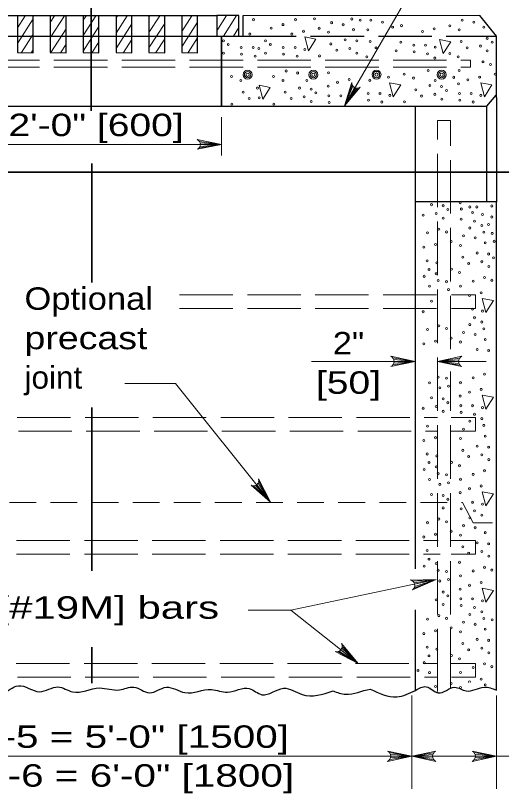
# Model space of a CAD drawing. Extents: x 1329.9 to 1363.9, y 715.5 to 737.5.
# Drawn here: x 1335.14 to 1338.52, y 728.7 to 734.11 of the extents above; entities that cross this region are included whole.
import ezdxf
from ezdxf.enums import TextEntityAlignment as Align

# ---------------------------------------------------------------- set-up
doc = ezdxf.new("R2010")
doc.units = 0
doc.header["$LTSCALE"] = 0.062
doc.linetypes.add('LONG_DASHED', pattern=[7.5, 6, -1.5])
doc.linetypes.add('MEDIUM_DASHED', pattern=[4.5, 3, -1.5])
doc.layers.add('1', color=7, linetype='Continuous', lineweight=13)

msp = doc.modelspace()

# ---------------------------------------------------------------- linework, layer by layer
at = {"layer": '1', "lineweight": 35}
for p, q in [((1335.66467, 735.20608), (1335.66467, 733.44408)), ((1335.66942, 733.07875), (1335.66942, 732.2515)), ((1335.66942, 731.38008), (1335.66942, 730.24558))]:
    msp.add_line(p, q, dxfattribs=at)
at = {"layer": '1', "lineweight": 25}
for p, q in [((1334.80542, 734.10575), (1336.53992, 734.10575)), ((1336.69283, 734.10575), (1336.53992, 734.10575)), ((1336.54033, 734.10575), (1336.54033, 733.96325)), ((1336.69283, 733.96325), (1336.69283, 734.10575)), ((1336.72025, 734.10508), (1336.72025, 733.96325)), ((1334.80125, 733.96325), (1336.54408, 733.96325)), ((1338.41808, 733.47675), (1338.48275, 733.55208)), ((1338.4845, 733.53675), (1338.4845, 732.81242)), ((1334.76992, 733.47708), (1336.57183, 733.47708)), ((1336.57192, 733.47717), (1338.41808, 733.47675)), ((1337.91867, 733.47675), (1337.91867, 730.259)), ((1338.41808, 732.81183), (1338.41808, 733.47675)), ((1338.4845, 732.81242), (1337.91867, 732.81242))]:
    msp.add_line(p, q, dxfattribs=at)
at = {"layer": '1'}
for p, q in [((1335.15233, 734.02008), (1335.20717, 734.1055)), ((1335.381, 733.951), (1335.48017, 734.10533)), ((1335.49117, 734.10533), (1335.38117, 734.10575)), ((1335.38117, 734.05867), (1335.41133, 734.10567)), ((1335.60983, 734.07442), (1335.62992, 734.10567)), ((1335.60983, 733.96683), (1335.69883, 734.10542)), ((1335.71992, 734.10533), (1335.61, 734.10575)), ((1335.83858, 733.98408), (1335.91658, 734.1055)), ((1335.83867, 734.09175), (1335.84767, 734.10567)), ((1335.94875, 734.10533), (1335.83875, 734.10575)), ((1336.06742, 733.9885), (1336.1425, 734.1055)), ((1336.1775, 734.10533), (1336.0675, 734.10575)), ((1336.0675, 734.09617), (1336.07358, 734.10567)), ((1336.29625, 734.10375), (1336.2975, 734.10567)), ((1336.29625, 733.99625), (1336.36633, 734.1055)), ((1336.40625, 734.10533), (1336.29633, 734.10575)), ((1336.54033, 734.00025), (1336.60817, 734.10575)), ((1336.58567, 733.96325), (1336.67725, 734.10575)), ((1335.15217, 733.9125), (1335.26233, 734.08392)), ((1335.83842, 733.87642), (1335.94858, 734.04792)), ((1336.06725, 733.881), (1336.17742, 734.05242)), ((1336.29608, 733.88858), (1336.40617, 734.06)), ((1335.38433, 733.84867), (1335.491, 734.01483)), ((1335.60967, 733.85917), (1335.71983, 734.03067)), ((1336.65467, 733.96325), (1336.69283, 734.02275)), ((1335.18025, 733.84867), (1335.26217, 733.97625)), ((1335.88958, 733.8485), (1335.9485, 733.94025)), ((1336.1155, 733.8485), (1336.17725, 733.94475)), ((1336.33942, 733.84858), (1336.406, 733.95233)), ((1336.57225, 733.96325), (1336.57225, 733.48492)), ((1336.68917, 733.96325), (1336.69283, 733.969)), ((1335.45317, 733.84842), (1335.49092, 733.90717)), ((1335.67183, 733.8485), (1335.71967, 733.923)), ((1335.24908, 733.84833), (1335.26208, 733.86858)), ((1335.48758, 733.84833), (1335.49083, 733.85342)), ((1338.30508, 733.79608), (1338.23917, 733.79608)), ((1338.30508, 733.74733), (1338.30508, 733.79608)), ((1338.30508, 733.74733), (1338.23775, 733.74733)), ((1336.83392, 733.62175), (1336.85958, 733.52442)), ((1337.48083, 733.6245), (1337.42808, 733.47783)), ((1337.48675, 733.61467), (1337.42808, 733.47783)), ((1337.4975, 733.60583), (1337.42808, 733.47783)), ((1337.50767, 733.60208), (1337.42808, 733.47783)), ((1337.51942, 733.60158), (1337.42808, 733.47783)), ((1336.57183, 733.40058), (1336.57183, 733.13242)), ((1336.41958, 733.2315), (1336.57183, 733.21025)), ((1336.41775, 733.18667), (1336.57183, 733.21025)), ((1336.42358, 733.19658), (1336.57183, 733.21025)), ((1336.42475, 733.221), (1336.57183, 733.21025)), ((1336.42633, 733.21025), (1336.57183, 733.21025)), ((1336.47292, 733.21025), (1336.57183, 733.21025)), ((1337.76458, 731.7265), (1337.91867, 731.7015)), ((1337.77042, 731.716), (1337.91867, 731.7015)), ((1338.22767, 731.72408), (1338.07542, 731.7015)), ((1337.19883, 731.7015), (1337.91867, 731.7015)), ((1337.76642, 731.679), (1337.91867, 731.7015)), ((1337.77158, 731.69017), (1337.91867, 731.7015)), ((1337.77317, 731.7015), (1337.91867, 731.7015)), ((1338.22258, 731.71292), (1338.07542, 731.7015)), ((1338.07542, 731.7015), (1338.41317, 731.7015)), ((1338.221, 731.7015), (1338.07542, 731.7015)), ((1338.22367, 731.68708), (1338.07542, 731.7015)), ((1338.2295, 731.67658), (1338.07542, 731.7015)), ((1336.25325, 731.54808), (1335.90092, 731.54808)), ((1336.91233, 730.7235), (1336.25325, 731.54808)), ((1336.82733, 730.855), (1336.91233, 730.7235)), ((1336.83108, 730.86633), (1336.91233, 730.7235)), ((1336.79783, 730.83533), (1336.91233, 730.7235)), ((1336.80925, 730.838), (1336.91233, 730.7235)), ((1336.81858, 730.84375), (1336.91233, 730.7235)), ((1337.05458, 729.97233), (1338.06583, 730.18458)), ((1337.90442, 730.17258), (1338.06583, 730.18458)), ((1337.91208, 730.16283), (1338.06583, 730.18458)), ((1337.91258, 730.126), (1338.06583, 730.18458)), ((1337.91608, 730.15217), (1338.06583, 730.18458)), ((1337.91633, 730.1375), (1338.06583, 730.18458)), ((1337.05458, 729.97233), (1336.75858, 729.97267)), ((1337.05458, 729.97233), (1337.52267, 729.60117)), ((1337.41175, 729.71908), (1337.52267, 729.60117)), ((1337.38075, 729.6835), (1337.52267, 729.60117)), ((1337.392, 729.68775), (1337.52267, 729.60117)), ((1337.40325, 729.69717), (1337.52267, 729.60117)), ((1337.40908, 729.70708), (1337.52267, 729.60117)), ((1338.09108, 729.3975), (1338.06908, 729.40175)), ((1338.06908, 729.40175), (1338.06983, 729.39883)), ((1337.8955, 729.37808), (1337.8955, 728.82842)), ((1337.8955, 729.37542), (1337.8955, 728.72917)), ((1338.4845, 729.37808), (1338.4845, 728.82842)), ((1338.4845, 729.37542), (1338.4845, 728.72917)), ((1337.23308, 728.95625), (1333.43842, 728.95625)), ((1337.8955, 728.95625), (1337.23308, 728.95625)), ((1337.74142, 728.98125), (1337.8955, 728.95625)), ((1337.74325, 728.93375), (1337.8955, 728.95625)), ((1337.74725, 728.97075), (1337.8955, 728.95625)), ((1337.74842, 728.94492), (1337.8955, 728.95625)), ((1337.74992, 728.95625), (1337.8955, 728.95625)), ((1338.04783, 728.97883), (1337.8955, 728.95625)), ((1338.04267, 728.96767), (1337.8955, 728.95625)), ((1339.24542, 728.95625), (1337.8955, 728.95625)), ((1338.04108, 728.95625), (1337.8955, 728.95625)), ((1338.04375, 728.94183), (1337.8955, 728.95625)), ((1338.04958, 728.93133), (1337.8955, 728.95625)), ((1338.4845, 728.95625), (1338.23675, 728.95625)), ((1338.33042, 728.98125), (1338.4845, 728.95625)), ((1338.33225, 728.93375), (1338.4845, 728.95625)), ((1338.33625, 728.97075), (1338.4845, 728.95625)), ((1338.33742, 728.94492), (1338.4845, 728.95625)), ((1338.33892, 728.95625), (1338.4845, 728.95625))]:
    msp.add_line(p, q, dxfattribs=at)
at = {"layer": '1', "linetype": 'LONG_DASHED', "lineweight": 25}
msp.add_line((1336.72025, 733.96325), (1338.4845, 733.96325), dxfattribs=at)
at = {"layer": '1', "linetype": 'LONG_DASHED'}
for p, q in [((1333.04633, 733.79608), (1338.30508, 733.79608)), ((1333.04633, 733.74733), (1338.30508, 733.74733)), ((1338.07492, 733.37567), (1338.16467, 733.37567)), ((1338.16467, 731.78575), (1338.16467, 733.37567)), ((1336.28017, 732.1655), (1338.077, 732.1655)), ((1338.17267, 732.1655), (1338.34008, 732.1655)), ((1338.34008, 732.1655), (1338.34008, 732.07058)), ((1336.28017, 732.07058), (1338.077, 732.07058)), ((1338.17267, 732.07058), (1338.34008, 732.07058)), ((1333.26267, 731.31067), (1338.07467, 731.31067)), ((1338.17033, 731.31067), (1338.34008, 731.31067)), ((1338.34008, 731.31067), (1338.34008, 731.21567)), ((1333.27175, 731.21567), (1338.07467, 731.21567)), ((1338.16583, 731.21567), (1338.34008, 731.21567)), ((1333.25808, 730.45583), (1338.07925, 730.45583)), ((1338.16583, 730.45583), (1338.34008, 730.45583)), ((1338.34008, 730.45583), (1338.34008, 730.36083)), ((1333.25808, 730.36083), (1338.09292, 730.36083)), ((1338.17033, 730.36083), (1338.34008, 730.36083)), ((1333.25575, 729.60092), (1338.07692, 729.60092)), ((1338.168, 729.60092), (1338.34008, 729.60092)), ((1338.34008, 729.60092), (1338.34008, 729.50592)), ((1333.26492, 729.50592), (1338.07692, 729.50592)), ((1338.17258, 729.50592), (1338.34008, 729.50592))]:
    msp.add_line(p, q, dxfattribs=at)
at = {"layer": '1', "linetype": 'MEDIUM_DASHED'}
msp.add_line((1338.32433, 730.57925), (1338.45892, 730.57925), dxfattribs=at)
at = {"layer": '1'}
for points in [[(1338.59067, 735.00633), (1338.312, 735.00633), (1337.42808, 733.47783)], [(1336.85958, 733.52442), (1336.91183, 733.6065), (1336.83392, 733.62175)], [(1337.47867, 733.64175), (1337.42808, 733.47783), (1337.53783, 733.60967)], [(1336.40367, 733.17658), (1336.57183, 733.21025), (1336.40367, 733.24383)], [(1334.76992, 733.21025), (1335.88917, 733.21025), (1336.57183, 733.21025)], [(1337.7505, 731.73717), (1337.91867, 731.7015), (1337.7505, 731.66592)], [(1338.24367, 731.66592), (1338.07542, 731.7015), (1338.24367, 731.73717)], [(1336.82975, 730.88458), (1336.91233, 730.7235), (1336.77808, 730.84042)], [(1337.90025, 730.1125), (1338.06583, 730.18458), (1337.88525, 730.18167)], [(1337.3625, 729.6845), (1337.52267, 729.60117), (1337.40683, 729.73975)], [(1337.72733, 728.99192), (1337.8955, 728.95625), (1337.72733, 728.92067)], [(1338.06375, 728.92067), (1337.8955, 728.95625), (1338.06375, 728.99192)], [(1338.31633, 728.99192), (1338.4845, 728.95625), (1338.31633, 728.92067)]]:
    msp.add_lwpolyline(points, dxfattribs=at)
at = {"layer": '1', "lineweight": 25}
for points in [[(1335.15242, 734.10575), (1335.15208, 733.84867), (1335.262, 733.84825), (1335.26242, 734.10533)], [(1335.38117, 734.10575), (1335.38083, 733.84867), (1335.49083, 733.84825), (1335.49117, 734.10533)], [(1335.61, 734.10575), (1335.60958, 733.84867), (1335.71958, 733.84825), (1335.71992, 734.10533)], [(1335.83875, 734.10575), (1335.83842, 733.84867), (1335.94833, 733.84825), (1335.94875, 734.10533)], [(1336.0675, 734.10575), (1336.06717, 733.84867), (1336.17717, 733.84825), (1336.1775, 734.10533)], [(1336.29633, 734.10575), (1336.296, 733.84867), (1336.40592, 733.84825), (1336.40625, 734.10533)], [(1338.4845, 733.53708), (1338.4845, 733.96325), (1338.37, 734.1075), (1336.72025, 734.10508)], [(1336.54408, 733.96325), (1336.57183, 733.96325), (1336.72025, 733.96325)], [(1336.57183, 733.47708), (1336.57225, 733.96325), (1336.57183, 733.47708)], [(1338.4845, 729.41567), (1338.4845, 729.46942), (1338.4845, 732.81242)], [(1337.91867, 729.97317), (1337.91867, 729.46942), (1337.91867, 729.41567)]]:
    msp.add_lwpolyline(points, dxfattribs=at)
at = {"layer": '1'}
for points in [[(1337.15117, 733.9575), (1337.17675, 733.86025), (1337.229, 733.94242)], [(1338.08908, 733.93925), (1338.11467, 733.84192), (1338.16692, 733.92408)], [(1337.74183, 733.63892), (1337.76742, 733.54158), (1337.81967, 733.62375)], [(1338.37617, 733.63892), (1338.40183, 733.54158), (1338.454, 733.62375)], [(1338.38633, 732.13925), (1338.412, 732.04192), (1338.46417, 732.12408)], [(1338.38633, 731.46758), (1338.412, 731.37025), (1338.46417, 731.45242)], [(1338.38633, 730.79592), (1338.412, 730.69858), (1338.46417, 730.78083)], [(1338.38633, 730.12433), (1338.412, 730.02692), (1338.46417, 730.10908)]]:
    msp.add_lwpolyline(points, close=True, dxfattribs=at)
at = {"layer": '1', "linetype": 'LONG_DASHED'}
for points in [[(1338.07492, 729.40692), (1338.07492, 729.46942), (1338.07492, 733.37567)], [(1338.16467, 729.43033), (1338.16467, 729.46942), (1338.16467, 731.63233)]]:
    msp.add_lwpolyline(points, dxfattribs=at)
at = {"layer": '1', "lineweight": 35}
for points in [[(1332.47342, 733.01742), (1338.878, 733.01742), (1338.878, 732.60617)], [(1335.66942, 729.71392), (1335.66942, 729.46942), (1335.66942, 729.46508)]]:
    msp.add_lwpolyline(points, dxfattribs=at)
at = {"layer": '1', "linetype": 'MEDIUM_DASHED'}
msp.add_lwpolyline([(1333.095, 730.71958), (1338.24792, 730.71958), (1338.32433, 730.57925)], dxfattribs=at)
at = {"layer": '1'}
for centre, radius in [((1336.75365, 733.6949), 0.03133), ((1336.75365, 733.6949), 0.0219), ((1337.21106, 733.6949), 0.03133), ((1337.21106, 733.6949), 0.0219), ((1337.65078, 733.69625), 0.03133), ((1337.65078, 733.69625), 0.0219), ((1338.10442, 733.6949), 0.03133), ((1338.10442, 733.6949), 0.0219), ((1336.75365, 733.6949), 0.01122), ((1337.21106, 733.6949), 0.01122), ((1337.65078, 733.69625), 0.01122), ((1338.10442, 733.6949), 0.01122)]:
    msp.add_circle(centre, radius, dxfattribs=at)
for centre, radius, start, end in [((1337.51477, 733.63765), 0.03631, 173.62389, 309.45001), ((1336.39006, 733.21026), 0.03631, 292.08605, 67.91218), ((1337.8788, 730.1441), 0.03822, 304.32142, 80.14755), ((1337.37353, 729.7211), 0.03822, 253.29077, 29.1169)]:
    msp.add_arc(centre, radius, start, end, dxfattribs=at)
for centre in [(1336.79528, 734.07782), (1337.00013, 734.04357), (1337.08779, 734.07782), (1337.21884, 734.08415), (1337.33874, 734.05694), (1337.41952, 734.04273), (1337.47953, 734.08263), (1337.53689, 734.07441), (1337.6122, 734.07411), (1337.69298, 734.0599), (1337.82488, 734.03633), (1338.16006, 734.0351), (1338.2466, 734.07411), (1338.32738, 734.0599), (1336.91703, 734.01916), (1337.14345, 733.99706), (1337.2522, 734.01793), (1337.31733, 733.99073), (1337.48973, 734.00825), (1337.59079, 734.0079), (1337.76319, 734.02542), (1337.96989, 733.99519), (1338.05131, 734.01422), (1338.22519, 734.0079), (1338.39759, 734.02542), (1336.58603, 733.93118), (1336.76953, 733.97803), (1336.87854, 733.93118), (1337.06204, 733.97803), (1337.43211, 733.93818), (1337.51294, 733.93118), (1337.60623, 733.92629), (1338.24062, 733.92629), (1338.42079, 733.94835), (1336.61971, 733.90459), (1336.70964, 733.88372), (1336.7919, 733.88372), (1336.83112, 733.87739), (1336.91222, 733.90459), (1337.00214, 733.88372), (1337.0844, 733.88372), (1337.33277, 733.90913), (1337.46552, 733.87739), (1337.64736, 733.88275), (1337.82007, 733.92176), (1337.91, 733.90088), (1337.99226, 733.90088), (1338.05987, 733.88728), (1338.28175, 733.88275), (1338.37337, 733.89456), (1338.45447, 733.92176), (1336.58688, 733.84442), (1336.71217, 733.83748), (1336.80559, 733.82388), (1336.87939, 733.84442), (1337.00468, 733.83748), (1337.09809, 733.82388), (1337.15202, 733.87012), (1337.25394, 733.82567), (1337.3739, 733.86558), (1337.51378, 733.84442), (1337.58392, 733.81928), (1337.78724, 733.86159), (1337.91253, 733.85465), (1338.00595, 733.84105), (1338.1618, 733.84284), (1338.21831, 733.81928), (1338.42164, 733.86159), (1338.05644, 733.81111), (1338.39166, 733.78452), (1338.4439, 733.76549), (1337.02154, 733.72112), (1338.01018, 733.72407), (1338.22519, 733.72491), (1336.6425, 733.68211), (1336.70763, 733.65491), (1336.935, 733.68211), (1337.00013, 733.65491), (1337.10232, 733.70691), (1337.16504, 733.65491), (1337.31733, 733.70774), (1337.46065, 733.66123), (1337.60475, 733.65626), (1337.73411, 733.6784), (1337.84286, 733.69928), (1337.90799, 733.67208), (1338.0584, 733.65491), (1338.18776, 733.67705), (1338.28709, 733.65937), (1338.36851, 733.6784), (1338.47726, 733.69928), (1336.8224, 733.60235), (1337.11491, 733.60235), (1337.31421, 733.615), (1337.37924, 733.6422), (1338.02276, 733.61952), (1338.10359, 733.61252), (1338.22207, 733.63217), (1336.72306, 733.5733), (1337.01557, 733.5733), (1337.19574, 733.59536), (1337.22941, 733.56877), (1337.31934, 733.54789), (1337.4016, 733.54789), (1337.5928, 733.56506), (1337.67506, 733.56506), (1337.74267, 733.55146), (1337.92343, 733.59047), (1337.96456, 733.54693), (1338.05617, 733.55874), (1338.13727, 733.58594), (1338.2272, 733.56506), (1338.30946, 733.56506), (1338.37707, 733.55146), (1336.76419, 733.52976), (1336.83482, 733.53429), (1337.0567, 733.52976), (1337.14832, 733.54157), (1337.19658, 733.5086), (1337.32188, 733.50166), (1337.59534, 733.51883), (1337.68875, 733.50523), (1337.8446, 733.50702), (1338.10444, 733.52577), (1338.22973, 733.51883), (1338.32315, 733.50523), (1336.64424, 733.48985), (1336.93675, 733.48985), (1338.03292, 732.79151), (1338.23223, 732.80416), (1338.11375, 732.78452), (1338.14743, 732.75793), (1338.24107, 732.76145), (1338.30052, 732.77539), (1338.31961, 732.73705), (1338.34882, 732.77539), (1338.45286, 732.78236), (1337.97471, 732.71892), (1338.06633, 732.73073), (1338.1146, 732.69776), (1338.23989, 732.69082), (1338.38723, 732.72345), (1338.45286, 732.70569), (1338.29984, 732.62914), (1338.33331, 732.67722), (1338.38379, 732.64728), (1338.43056, 732.65342), (1338.0058, 732.59534), (1338.08462, 732.62069), (1338.13685, 732.60166), (1338.25676, 732.57446), (1338.39754, 732.60015), (1338.4549, 732.59192), (1338.17021, 732.53545), (1338.33754, 732.56024), (1338.40774, 732.52577), (1338.46944, 732.53668), (1337.98005, 732.49554), (1338.06147, 732.51457), (1338.23535, 732.50825), (1338.25078, 732.42664), (1338.35012, 732.45569), (1338.43095, 732.4487), (1338.46463, 732.42211), (1338.00242, 732.40123), (1338.07003, 732.38763), (1338.29191, 732.3831), (1338.38353, 732.39491), (1338.4318, 732.36194), (1338.01611, 732.3414), (1338.0666, 732.31146), (1338.17196, 732.34319), (1338.22847, 732.31963), (1337.98264, 732.29332), (1338.08034, 732.26433), (1338.1377, 732.2561), (1338.323, 732.25951), (1338.40182, 732.28487), (1338.45405, 732.26584), (1338.02034, 732.22442), (1338.15224, 732.20086), (1338.23535, 732.22526), (1338.29725, 732.15972), (1338.37867, 732.17875), (1338.03292, 732.11987), (1337.97471, 732.04727), (1338.31961, 732.06541), (1338.38723, 732.05181), (1338.33331, 732.00558), (1338.0058, 731.92369), (1338.08462, 731.94905), (1338.13685, 731.93002), (1338.29984, 731.9575), (1338.38379, 731.97563), (1338.39754, 731.92851), (1338.25676, 731.90282), (1338.33754, 731.8886), (1337.98005, 731.8239), (1338.06147, 731.84293), (1338.17021, 731.8638), (1338.23535, 731.8366), (1338.40774, 731.85412), (1338.35012, 731.78405), (1338.43095, 731.77705), (1338.40182, 731.61322), (1338.02034, 731.55278), (1338.08034, 731.59268), (1338.1377, 731.58446), (1338.23535, 731.55362), (1338.323, 731.58787), (1338.09054, 731.5183), (1338.15224, 731.52921), (1338.37867, 731.5071), (1338.03292, 731.44822), (1338.11375, 731.44123), (1338.23223, 731.46087), (1338.29725, 731.48807), (1338.06633, 731.38744), (1338.14743, 731.41464), (1338.23735, 731.39376), (1338.31961, 731.39376), (1337.97471, 731.37563), (1338.1146, 731.35447), (1338.23989, 731.34753), (1338.33331, 731.33393), (1338.38723, 731.38016), (1338.29984, 731.28585), (1338.38379, 731.30399), (1338.0058, 731.25205), (1338.25676, 731.23117), (1338.39754, 731.25686), (1338.06147, 731.17128), (1338.40774, 731.18248), (1337.98005, 731.15225), (1338.23535, 731.16496), (1338.35012, 731.1124), (1338.00242, 731.05794), (1338.25078, 731.08335), (1338.43095, 731.1054), (1338.07003, 731.04434), (1338.29191, 731.03981), (1338.38353, 731.05162), (1338.4318, 731.01865), (1337.98264, 730.95003), (1338.01611, 730.99811), (1338.0666, 730.96816), (1338.17196, 730.9999), (1338.22847, 730.97634), (1338.08034, 730.92104), (1338.1377, 730.91281), (1338.323, 730.91622), (1338.40182, 730.94158), (1338.02034, 730.88113), (1338.09054, 730.84665), (1338.15224, 730.85757), (1338.23535, 730.88197), (1338.23223, 730.78923), (1338.29725, 730.81643), (1338.37867, 730.83546), (1338.03292, 730.77658), (1338.11375, 730.76958), (1338.14743, 730.743), (1338.1146, 730.68283), (1338.31961, 730.72212), (1338.38723, 730.70852), (1338.23989, 730.67589), (1338.33331, 730.66229), (1338.38379, 730.63234), (1338.0058, 730.5804), (1338.08462, 730.60576), (1338.13685, 730.58673), (1338.29984, 730.61421), (1338.17021, 730.52051), (1338.25676, 730.55952), (1338.33754, 730.54531), (1337.98005, 730.48061), (1338.06147, 730.49964), (1338.23535, 730.49331), (1338.40774, 730.51083), (1338.25078, 730.41171), (1338.35012, 730.44075), (1338.43095, 730.43376), (1338.00242, 730.3863), (1338.29191, 730.36816), (1338.38353, 730.37997), (1338.01611, 730.32646), (1338.22847, 730.30469), (1338.4318, 730.347), (1337.98264, 730.27838), (1338.0666, 730.29652), (1338.08034, 730.24939), (1338.40182, 730.26993), (1338.45405, 730.2509), (1338.1377, 730.24116), (1338.23535, 730.21032), (1338.323, 730.24458), (1338.09054, 730.17501), (1338.15224, 730.18592), (1338.29725, 730.14478), (1338.37867, 730.16381), (1338.11375, 730.09794), (1338.23223, 730.11758), (1338.06633, 730.04415), (1338.14743, 730.07135), (1338.23735, 730.05047), (1338.31961, 730.05047), (1338.38723, 730.03687), (1338.1146, 730.01118), (1338.23989, 730.00424), (1338.33331, 729.99064), (1338.08462, 729.93411), (1338.29984, 729.94256), (1338.38379, 729.9607), (1338.0058, 729.90876), (1338.13685, 729.91508), (1338.25676, 729.88788), (1338.33754, 729.87366), (1338.39754, 729.91357), (1338.4549, 729.90534), (1338.06147, 729.82799), (1338.17021, 729.84887), (1338.23535, 729.82167), (1338.40774, 729.83918), (1337.98005, 729.80896), (1338.35012, 729.76911), (1338.43095, 729.76211), (1338.00242, 729.71465), (1338.25078, 729.74006), (1338.38353, 729.70833), (1338.01611, 729.65482), (1338.07003, 729.70105), (1338.17196, 729.65661), (1338.29191, 729.69652), (1338.4318, 729.67536), (1337.98264, 729.60674), (1338.22847, 729.63304), (1338.40182, 729.59829), (1337.93956, 729.55206), (1338.323, 729.57293), (1338.45405, 729.57926), (1338.02034, 729.53784), (1338.23535, 729.53868), (1338.37867, 729.49217), (1338.06147, 729.44129), (1338.17021, 729.46217), (1338.40774, 729.45249), (1338.23535, 729.43497)]:
    msp.add_ellipse(centre, major_axis=(0, 0.00718), ratio=0.944544, dxfattribs=at)
for centre, major_axis, start_param, end_param in [((1337.73683, 731.70153), (0, -0.03844), 0.3855052, 2.7561184), ((1338.25728, 731.70154), (0, 0.03844), 0.3855052, 2.7561184), ((1336.79514, 730.87378), (0.00888, -0.0374), 5.5493156, 7.9199288), ((1338.29725, 729.47314), (0, 0.00718), 4.1740079, 8.3923627), ((1337.71365, 728.95628), (0, -0.03844), 0.3855052, 2.7561184), ((1338.07739, 728.95629), (0, 0.03844), 0.3855052, 2.7561184), ((1338.30264, 728.95628), (0, -0.03844), 0.3855052, 2.7561184)]:
    msp.add_ellipse(centre, major_axis=major_axis, ratio=0.944544, start_param=start_param, end_param=end_param, dxfattribs=at)
at = {"layer": '1', "lineweight": 25}
for points in [[(1333.71783, 729.43742), (1333.74617, 729.44542), (1333.87192, 729.41275), (1334.00608, 729.43875), (1334.11883, 729.3935), (1334.27358, 729.438), (1334.38633, 729.39758), (1334.501, 729.44683), (1334.61375, 729.40833), (1334.71533, 729.43617), (1334.828, 729.4045), (1334.93892, 729.42642), (1335.04608, 729.39958), (1335.15892, 729.44692), (1335.307, 729.40475), (1335.43475, 729.43842), (1335.53625, 729.40375), (1335.72358, 729.43092), (1335.86242, 729.41792), (1335.96125, 729.43683), (1336.07208, 729.39742), (1336.18867, 729.436), (1336.31817, 729.3985), (1336.50175, 729.42075), (1336.6145, 729.40175), (1336.76542, 729.42783), (1336.854, 729.38433), (1337.004, 729.42892), (1337.1335, 729.38567), (1337.34833, 729.41017)], [(1337.92258, 729.41408), (1337.99625, 729.43967), (1338.08, 729.39625), (1338.19475, 729.43575), (1338.27483, 729.41075), (1338.39975, 729.43667), (1338.4845, 729.41567)], [(1337.34833, 729.41017), (1337.43558, 729.38775), (1337.60608, 729.4235), (1337.6065, 729.42358)], [(1337.60608, 729.4235), (1337.79292, 729.36892), (1337.92258, 729.41408)]]:
    msp.add_spline(points, degree=3, dxfattribs=at)

# ---------------------------------------------------------------- texts
at = {"layer": '1'}
for s, width, p in [('2\'-0" [600]', 1.3, (1335.69967, 733.26808)), ('2"', 1.15, (1337.45579, 731.75058)), ('[50]', 1.3, (1337.45579, 731.4765))]:
    msp.add_text(s, height=0.156, dxfattribs=dict(at, width=width)).set_placement(p, align=Align.CENTER)
for s, width, p in [('Optional', 1.15, (1335.20167, 732.06058)), ('precast', 1.25, (1335.20167, 731.7865)), ('joint', 1.05, (1335.20167, 731.51242)), ('#6 [#19M] bars', 1.4, (1334.60733, 729.9125)), ('CB No 2-5 = 5\'-0" [1500]', 1.35, (1333.98433, 729.01475)), ('CB No. 2-6 = 6\'-0" [1800]', 1.35, (1333.94167, 728.74467))]:
    msp.add_text(s, height=0.156, dxfattribs=dict(at, width=width)).set_placement(p)

doc.saveas('drawing.dxf')
